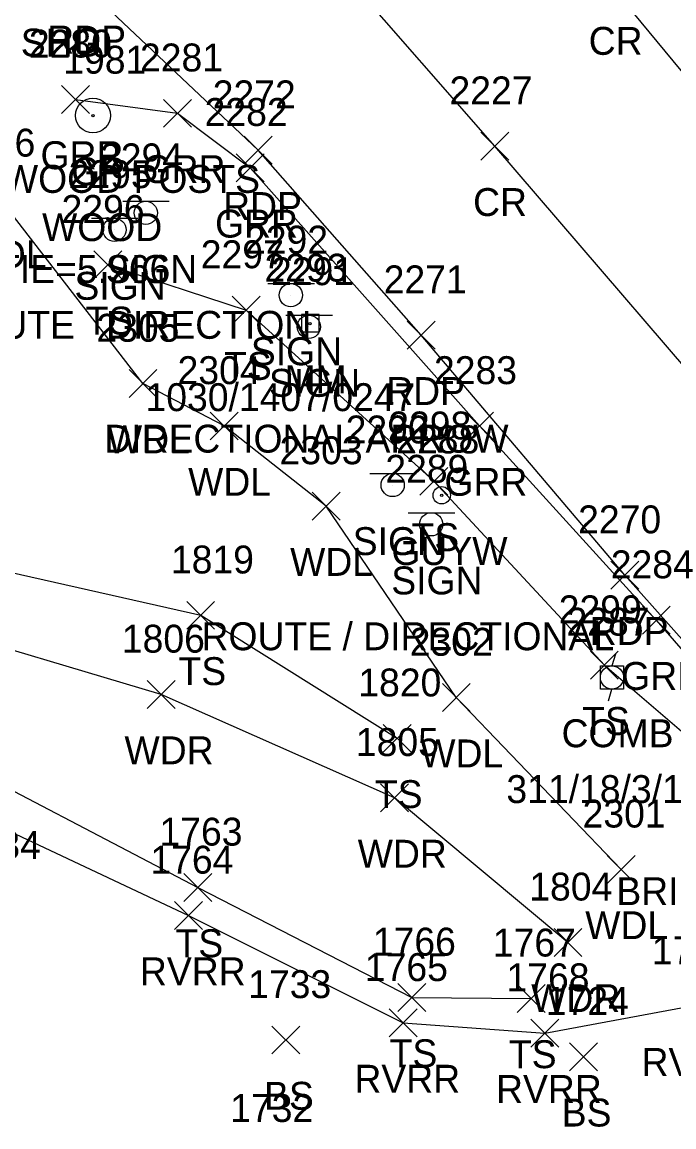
# Model space of a CAD drawing. Extents: x 1616726 to 1619875, y 273782 to 276557.
# Drawn here: x 1616883.5 to 1616930.2, y 276294.1 to 276373.3 of the extents above; entities that cross this region are included whole.
import ezdxf

# ---------------------------------------------------------------- set-up
doc = ezdxf.new("R2010")
doc.units = 0
for name, color, linetype in [('L_A', 7, 'Continuous'), ('L_I', 7, 'Continuous'), ('L_TIC', 7, 'Continuous'), ('LAWA', 7, 'Continuous'), ('LAWE', 7, 'Continuous'), ('LELB', 7, 'Continuous'), ('P_A', 7, 'Continuous'), ('P_I', 7, 'Continuous'), ('P_TIC', 7, 'Continuous'), ('PET', 7, 'Continuous'), ('PRC', 7, 'Continuous'), ('R_A', 7, 'Continuous'), ('R_C', 7, 'Continuous'), ('R_I', 7, 'Continuous'), ('R_TIC', 7, 'Continuous'), ('RGP', 7, 'Continuous'), ('RGR', 7, 'Continuous'), ('S_A', 7, 'Continuous'), ('S_C', 7, 'Continuous'), ('S_I', 7, 'Continuous'), ('SRM', 7, 'Continuous'), ('SSGN', 7, 'Continuous'), ('U_A', 7, 'Continuous'), ('U_C', 7, 'Continuous'), ('U_I', 7, 'Continuous'), ('UP', 7, 'Continuous'), ('UPGW', 7, 'Continuous')]:
    doc.layers.add(name, color=color, linetype=linetype)

msp = doc.modelspace()

# ---------------------------------------------------------------- linework, layer by layer
at = {"layer": 'L_TIC'}
for points in [[(1616888.608, 276354.888), (1616890.608, 276356.888)], [(1616890.608, 276354.888), (1616888.608, 276356.888)], [(1616898.528, 276351.642), (1616900.528, 276353.642)], [(1616900.528, 276351.642), (1616898.528, 276353.642)], [(1616891.129, 276346.375), (1616893.129, 276348.375)], [(1616893.129, 276346.375), (1616891.129, 276348.375)], [(1616896.946, 276343.338), (1616898.946, 276345.338)], [(1616898.946, 276343.338), (1616896.946, 276345.338)], [(1616911.966, 276339.373), (1616913.966, 276341.373)], [(1616913.966, 276339.373), (1616911.966, 276341.373)], [(1616904.255, 276337.598), (1616906.255, 276339.598)], [(1616906.255, 276337.598), (1616904.255, 276339.598)], [(1616895.265, 276329.77), (1616897.265, 276331.77)], [(1616897.265, 276329.77), (1616895.265, 276331.77)], [(1616924.193, 276326.199), (1616926.193, 276328.199)], [(1616926.193, 276326.199), (1616924.193, 276328.199)], [(1616892.44, 276324.097), (1616894.44, 276326.097)], [(1616894.44, 276324.097), (1616892.44, 276326.097)], [(1616913.583, 276323.874), (1616915.583, 276325.874)], [(1616915.583, 276323.874), (1616913.583, 276325.874)], [(1616909.34, 276320.957), (1616911.34, 276322.957)], [(1616911.34, 276320.957), (1616909.34, 276322.957)], [(1616909.156, 276316.687), (1616911.156, 276318.687)], [(1616911.156, 276316.687), (1616909.156, 276318.687)], [(1616925.406, 276311.564), (1616927.406, 276313.564)], [(1616927.406, 276311.564), (1616925.406, 276313.564)], [(1616895.051, 276310.268), (1616897.051, 276312.268)], [(1616897.051, 276310.268), (1616895.051, 276312.268)], [(1616894.397, 276308.259), (1616896.397, 276310.259)], [(1616896.397, 276308.259), (1616894.397, 276310.259)], [(1616921.586, 276306.333), (1616923.586, 276308.333)], [(1616923.586, 276306.333), (1616921.586, 276308.333)], [(1616910.397, 276302.387), (1616912.397, 276304.387)], [(1616912.397, 276302.387), (1616910.397, 276304.387)], [(1616918.942, 276302.319), (1616920.942, 276304.319)], [(1616920.942, 276302.319), (1616918.942, 276304.319)], [(1616909.771, 276300.56), (1616911.771, 276302.56)], [(1616911.771, 276300.56), (1616909.771, 276302.56)], [(1616901.363, 276299.339), (1616903.363, 276301.339)], [(1616903.363, 276299.339), (1616901.363, 276301.339)], [(1616919.919, 276299.828), (1616921.919, 276301.828)], [(1616921.919, 276299.828), (1616919.919, 276301.828)], [(1616922.693, 276298.139), (1616924.693, 276300.139)], [(1616924.693, 276298.139), (1616922.693, 276300.139)]]:
    msp.add_lwpolyline(points, dxfattribs=at)
at = {"layer": 'LAWA'}
for points in [[(1616926.406, 276312.564), (1616914.583, 276324.874), (1616905.255, 276338.598), (1616897.946, 276344.338), (1616892.129, 276347.375), (1616881.855, 276360.642), (1616871.248, 276371.071), (1616853.281, 276386.357), (1616841.144, 276384.083), (1616808.16, 276401.964), (1616800.624, 276406.172), (1616775.17, 276427.702), (1616751.596, 276451.278), (1616729.597, 276454.598)], [(1616922.586, 276307.333), (1616910.156, 276317.687), (1616893.44, 276325.097), (1616875.944, 276330.293), (1616859.853, 276336.016), (1616845.112, 276340.688), (1616828.663, 276349.596), (1616811.427, 276357.157), (1616790.231, 276359.66)]]:
    msp.add_lwpolyline(points, dxfattribs=at)
at = {"layer": 'LAWE'}
msp.add_lwpolyline([(1616789.066, 276346.617), (1616813.729, 276340.234), (1616836.199, 276333.67), (1616856.332, 276327.47), (1616874.716, 276318.98), (1616895.397, 276309.259), (1616910.771, 276301.56), (1616920.919, 276300.828), (1616931.346, 276302.765), (1616941.571, 276299.741), (1616947.812, 276295.799), (1616953.389, 276297.474), (1616960.888, 276300.059), (1616975.487, 276304.634), (1616989.935, 276306.407), (1617005.692, 276306.569), (1617020.087, 276309.056), (1617036.575, 276315.223), (1617052.505, 276318.389), (1617064.656, 276321.245), (1617083.344, 276325.98), (1617106.129, 276330.762), (1617129.705, 276333.809)], dxfattribs=at)
at = {"layer": 'LELB'}
for points in [[(1616788.698, 276366.665), (1616816.671, 276363.474), (1616839.333, 276351.688), (1616859.658, 276341.531), (1616877.714, 276334.951), (1616896.265, 276330.77), (1616910.34, 276321.957)], [(1616889.608, 276355.888), (1616899.528, 276352.642), (1616912.966, 276340.373), (1616925.193, 276327.199), (1616935.405, 276318.449)], [(1616788.767, 276349.669), (1616814.797, 276342.25), (1616838.024, 276336.69), (1616857.128, 276329.779), (1616876.235, 276321.642), (1616896.051, 276311.268), (1616911.397, 276303.387), (1616919.942, 276303.319)]]:
    msp.add_lwpolyline(points, dxfattribs=at)
at = {"layer": 'P_TIC'}
for points in [[(1616916.352, 276363.385), (1616918.352, 276365.385)], [(1616918.352, 276363.385), (1616916.352, 276365.385)], [(1616899.384, 276363.101), (1616901.384, 276365.101)], [(1616901.384, 276363.101), (1616899.384, 276365.101)], [(1616911.071, 276349.842), (1616913.071, 276351.842)], [(1616913.071, 276349.842), (1616911.071, 276351.842)], [(1616925.659, 276332.645), (1616927.659, 276334.645)], [(1616927.659, 276332.645), (1616925.659, 276334.645)]]:
    msp.add_lwpolyline(points, dxfattribs=at)
at = {"layer": 'PET'}
msp.add_lwpolyline([(1617014.404, 276374.536), (1616987.83, 276362.226), (1616976.678, 276357.843), (1616969.871, 276350.951), (1616965.537, 276344.162), (1616964.241, 276339.945), (1616963.659, 276334.926), (1616964.456, 276330.122), (1616966.241, 276325.428), (1616953.454, 276321.458), (1616940.91, 276317.633), (1616926.659, 276333.645), (1616912.071, 276350.842), (1616900.384, 276364.101), (1616887.78, 276376.027)], dxfattribs=at)
at = {"layer": 'PRC'}
for points in [[(1616953.087, 276321.774), (1616937.295, 276341.184), (1616917.352, 276364.385), (1616896.093, 276388.679), (1616870.6, 276416.951), (1616844.423, 276444.9), (1616816.583, 276473.522), (1616795.842, 276493.985), (1616777.166, 276512.186)], [(1616895.968, 276413.196), (1616909.569, 276395.506), (1616925.638, 276375.937), (1616938.47, 276360.406), (1616951.957, 276344.025), (1616962.869, 276330.949)]]:
    msp.add_lwpolyline(points, dxfattribs=at)
at = {"layer": 'R_TIC'}
for points in [[(1616886.297, 276366.742), (1616888.297, 276368.742)], [(1616888.297, 276366.742), (1616886.297, 276368.742)], [(1616893.607, 276365.745), (1616895.607, 276367.745)], [(1616895.607, 276365.745), (1616893.607, 276367.745)], [(1616898.806, 276361.841), (1616900.806, 276363.841)], [(1616900.806, 276361.841), (1616898.806, 276363.841)], [(1616915.244, 276343.338), (1616917.244, 276345.338)], [(1616917.244, 276343.338), (1616915.244, 276345.338)], [(1616927.916, 276329.424), (1616929.916, 276331.424)], [(1616929.916, 276329.424), (1616927.916, 276331.424)]]:
    msp.add_lwpolyline(points, dxfattribs=at)
at = {"layer": 'RGP'}
msp.add_line((1616888.542, 276366.587), (1616888.542, 276366.587), dxfattribs=at)
for radius in [1.25, 0.0833]:
    msp.add_circle((1616888.542, 276366.587), radius, dxfattribs=at)
at = {"layer": 'RGR'}
msp.add_lwpolyline([(1616887.297, 276367.742), (1616894.607, 276366.745), (1616899.806, 276362.841), (1616916.244, 276344.338), (1616928.916, 276330.424), (1616939.713, 276318.033)], dxfattribs=at)
at = {"layer": 'SRM'}
for p, q in [((1616904.744, 276352.339), (1616903.494, 276352.339)), ((1616903.494, 276352.339), (1616903.494, 276351.089)), ((1616904.744, 276352.339), (1616903.494, 276352.339)), ((1616903.494, 276352.339), (1616903.494, 276351.089)), ((1616904.744, 276351.089), (1616904.744, 276352.339)), ((1616904.744, 276351.089), (1616904.744, 276352.339)), ((1616903.494, 276351.089), (1616904.744, 276351.089)), ((1616903.494, 276351.089), (1616904.744, 276351.089))]:
    msp.add_line(p, q, dxfattribs=at)
msp.add_circle((1616904.095, 276351.677), 0.0833, dxfattribs=at)
at = {"layer": 'SSGN'}
for p, q in [((1616890.682, 276360.44), (1616894.015, 276360.44)), ((1616888.432, 276359.236), (1616891.765, 276359.236)), ((1616892.329, 276359.607), (1616892.329, 276359.607)), ((1616890.079, 276358.403), (1616890.079, 276358.403)), ((1616901.075, 276354.546), (1616904.409, 276354.546)), ((1616902.722, 276353.713), (1616902.722, 276353.713)), ((1616902.37, 276352.283), (1616905.704, 276352.283)), ((1616904.017, 276351.45), (1616904.017, 276351.45)), ((1616908.374, 276340.94), (1616911.708, 276340.94)), ((1616910.021, 276340.107), (1616910.021, 276340.107)), ((1616911.136, 276338.122), (1616914.47, 276338.122)), ((1616912.783, 276337.289), (1616912.783, 276337.289))]:
    msp.add_line(p, q, dxfattribs=at)
for centre in [(1616892.329, 276359.607), (1616890.079, 276358.403), (1616902.722, 276353.713), (1616904.017, 276351.45), (1616910.021, 276340.107), (1616912.783, 276337.289)]:
    msp.add_circle(centre, 0.833, dxfattribs=at)
at = {"layer": 'UP'}
for p, q in [((1616925.99, 276327.983), (1616925.74, 276327.15)), ((1616924.907, 276325.483), (1616924.907, 276327.15)), ((1616924.907, 276327.15), (1616926.573, 276327.15)), ((1616926.573, 276327.15), (1616926.573, 276325.483)), ((1616925.74, 276326.317), (1616925.74, 276326.317)), ((1616926.573, 276325.483), (1616924.907, 276325.483)), ((1616925.49, 276324.65), (1616925.74, 276325.483))]:
    msp.add_line(p, q, dxfattribs=at)
msp.add_circle((1616925.74, 276326.317), 0.833, dxfattribs=at)
at = {"layer": 'UPGW'}
for radius in [0.625, 0.0833]:
    msp.add_circle((1616913.538, 276339.373), radius, dxfattribs=at)

# ---------------------------------------------------------------- texts
at = {"layer": 'L_A'}
for s, p in [('WDL', (1616879.273, 276355.642)), ('TS', (1616888.018, 276350.888)), ('TS', (1616897.938, 276347.642)), ('WDL', (1616889.546, 276342.375)), ('WDL', (1616895.363, 276339.338)), ('TS', (1616911.376, 276335.373)), ('WDL', (1616902.673, 276333.598)), ('TS', (1616894.674, 276325.77)), ('TS', (1616923.602, 276322.199)), ('WDR', (1616890.802, 276320.097)), ('WDL', (1616912, 276319.874)), ('TS', (1616908.749, 276316.957)), ('WDR', (1616907.518, 276312.687)), ('WDL', (1616923.823, 276307.564)), ('TS', (1616894.46, 276306.268)), ('RVRR', (1616891.909, 276304.259)), ('WDR', (1616919.948, 276302.333)), ('TS', (1616909.806, 276298.387)), ('TS', (1616918.352, 276298.319)), ('RVRR', (1616927.858, 276297.765)), ('RVRR', (1616907.283, 276296.56)), ('BS', (1616900.804, 276295.339)), ('RVRR', (1616917.431, 276295.828)), ('BS', (1616922.134, 276294.139))]:
    msp.add_text(s, height=2, dxfattribs=at).set_placement(p)
at = {"layer": 'L_I'}
for s, p in [('2306', (1616878.462, 276363.642)), ('2296', (1616886.293, 276358.888)), ('2297', (1616896.269, 276355.642)), ('2305', (1616888.79, 276350.375)), ('2304', (1616894.608, 276347.338)), ('2298', (1616909.707, 276343.373)), ('2303', (1616901.917, 276341.598)), ('1819', (1616894.131, 276333.77)), ('2299', (1616921.925, 276330.199)), ('1806', (1616890.613, 276328.097)), ('2302', (1616911.244, 276327.874)), ('1820', (1616907.56, 276324.957)), ('1805', (1616907.384, 276320.687)), ('2301', (1616923.634, 276315.564)), ('1763', (1616893.311, 276314.268)), ('1734', (1616878.859, 276313.314)), ('1764', (1616892.657, 276312.259)), ('1804', (1616919.814, 276310.333)), ('1766', (1616908.602, 276306.387)), ('1767', (1616917.202, 276306.319)), ('1769', (1616928.598, 276305.765)), ('1765', (1616908.031, 276304.56)), ('1768', (1616918.179, 276303.828)), ('1733', (1616899.67, 276303.339)), ('1724', (1616921, 276302.139)), ('1732', (1616898.381, 276294.463))]:
    msp.add_text(s, height=2, dxfattribs=at).set_placement(p)
at = {"layer": 'P_A'}
for s, p in [('SHG', (1616883.371, 276370.814)), ('RDP', (1616885.268, 276371.027)), ('CR', (1616924.071, 276370.937)), ('CR', (1616915.785, 276359.385)), ('RDP', (1616897.873, 276359.101)), ('RDP', (1616909.559, 276345.842)), ('RDP', (1616924.147, 276328.645))]:
    msp.add_text(s, height=2, dxfattribs=at).set_placement(p)
at = {"layer": 'P_I'}
for s, p in [('2227', (1616914.092, 276367.385)), ('2272', (1616897.125, 276367.101)), ('2271', (1616909.378, 276353.842)), ('2270', (1616923.313, 276336.645))]:
    msp.add_text(s, height=2, dxfattribs=at).set_placement(p)
at = {"layer": 'R_A'}
for s, p in [('GRR', (1616884.785, 276362.742)), ('GP', (1616886.975, 276361.587)), ('GRR', (1616892.096, 276361.745)), ('GRR', (1616897.295, 276357.841)), ('GRR', (1616913.732, 276339.338)), ('GRR', (1616926.404, 276325.424))]:
    msp.add_text(s, height=2, dxfattribs=at).set_placement(p)
at = {"layer": 'R_C'}
for s, p in [('SGR W/ WOOD POSTS', (1616871.542, 276361.044)), ('WOOD', (1616884.896, 276357.587)), ('TIE=5.966', (1616881.668, 276354.587))]:
    msp.add_text(s, height=2, dxfattribs=at).set_placement(p)
at = {"layer": 'R_I'}
for s, p in [('2280', (1616883.951, 276370.742)), ('1981', (1616886.416, 276369.587)), ('2281', (1616891.914, 276369.745)), ('2282', (1616896.547, 276365.841)), ('2283', (1616912.984, 276347.338)), ('2284', (1616925.656, 276333.424))]:
    msp.add_text(s, height=2, dxfattribs=at).set_placement(p)
at = {"layer": 'S_A'}
for s, p in [('SIGN', (1616889.467, 276354.587)), ('SIGN', (1616887.217, 276353.383)), ('SIGN', (1616899.86, 276348.692)), ('MM', (1616902.283, 276346.682)), ('SIGN', (1616901.155, 276346.43)), ('SIGN', (1616907.159, 276335.087)), ('SIGN', (1616909.921, 276332.269))]:
    msp.add_text(s, height=2, dxfattribs=at).set_placement(p)
at = {"layer": 'S_C'}
for s, p in [('ROUTE   DIRECTION', (1616877.892, 276350.587)), ('1030/1407/0247', (1616892.31, 276345.403)), ('DIRECTIONAL ARROW', (1616889.352, 276342.43)), ('ROUTE / DIRECTIONAL', (1616896.323, 276328.269)), ('BRIDGE WARNING', (1616926.051, 276310.004))]:
    msp.add_text(s, height=2, dxfattribs=at).set_placement(p)
at = {"layer": 'S_I'}
for s, p in [('2294', (1616889.049, 276362.587)), ('2295', (1616886.799, 276361.383)), ('2292', (1616899.443, 276356.692)), ('2293', (1616900.834, 276354.682)), ('2291', (1616901.305, 276354.43)), ('2290', (1616906.655, 276343.087)), ('2289', (1616909.496, 276340.269))]:
    msp.add_text(s, height=2, dxfattribs=at).set_placement(p)
at = {"layer": 'U_A'}
for s, p in [('GUYW', (1616909.931, 276334.373)), ('COMB', (1616922.126, 276321.317))]:
    msp.add_text(s, height=2, dxfattribs=at).set_placement(p)
at = {"layer": 'U_C'}
msp.add_text('311/18/3/16', height=2, dxfattribs=at).set_placement((1616918.173, 276317.317))
at = {"layer": 'U_I'}
for s, p in [('2288', (1616910.278, 276342.373)), ('2287', (1616922.48, 276329.317))]:
    msp.add_text(s, height=2, dxfattribs=at).set_placement(p)

doc.saveas('drawing.dxf')
